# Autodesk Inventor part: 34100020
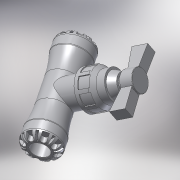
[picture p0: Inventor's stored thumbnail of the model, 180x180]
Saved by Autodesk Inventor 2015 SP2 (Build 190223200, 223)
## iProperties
Created: 2016-12
Part Number: 34100020
Material: PVC-Piping
Description: Plasson COMPRESSION STOPTAP 20 SERIES 1
Document SubType Name: Modeling
Designer: KIM
Mass: 61.7504 g
Surface Area: 140.097 cm^2
Volume: 44.1074 cm^3
Density: 1.4 g/cm^3
Appearance: Smooth - White
Author: KIM
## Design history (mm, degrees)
derived "03410.ipt"
feature "Solid1::03410.ipt" dims "ScaleForDerivedMember" = 10
feature "Solid2::03410.ipt" dims "ScaleForDerivedMember" = 10
tag "TaggingFeature1"
body "Solid1"
other parameters: "d1" = 18.9 [user parameter], "d3" = 25 [user parameter], "d4" = 41 [user parameter], "d6" = 45 [user parameter], "d8" = 34.85 [user parameter], "d13" = 6.4 [user parameter], "d14" = 6.4 [user parameter], "d15" = 0 [user parameter], "d17" = 360 deg [user parameter], "d19" = 8 deg [user parameter], "d20" = 0.4 [user parameter], "d21" = 0.4 [user parameter], "d22" = 8 deg [user parameter], "d24" = 0 [user parameter], "d26" = 360 deg [user parameter], "d33" = 4.1 [user parameter], "d35" = 2.5 [user parameter], "d65" = 0.41 [user parameter], "d69" = 123 [user parameter], "d72" = 41 [user parameter], "d73" = 25 [user parameter], "d74" = 18.9 [user parameter], "d75" = 61.5 [user parameter], "d76" = 2.5 [user parameter], "d77" = 45 [user parameter], "d80" = 6.4 [user parameter], "d82" = 6.4 [user parameter], "d83" = 0 [user parameter], "d85" = 360 deg [user parameter], "d92" = 0 [user parameter], "d94" = 360 deg [user parameter], "d96" = 89 [user parameter], "d97" = 41 [user parameter], "d98" = 32.8 [user parameter], "d99" = 32.8 [user parameter], "d100" = 135 deg [user parameter], "d101" = 16.4 [user parameter], "d102" = 70 deg [user parameter], "d103" = 48.95 [user parameter], "d104" = 71.2 [user parameter], "d105" = 62.3 [user parameter], "d107" = 75.65 [user parameter], "d108" = 73.8 [user parameter], "d110" = 12.015 [user parameter], "d111" = 4.005 [user parameter], "d112" = 12.3 [user parameter], "d113" = 0 [user parameter], "d114" = 43.05 [user parameter], "d115" = 4.1 [user parameter], "d116" = 0 [user parameter], "d117" = 4.1 [user parameter], "d119" = 0 [user parameter], "d121" = 360 deg [user parameter], "d126" = 0.4 [user parameter], "d127" = 0.4 [user parameter], "d128" = 8 deg [user parameter], "d129" = 8 deg [user parameter], "d130" = 0.41 [user parameter], "d132" = 0 [user parameter], "E_" = 41 [user parameter], "H_" = 123 [user parameter], "l_" = 45 [user parameter], "A_" = 89 [user parameter], "l_1" = 45 [user parameter], "E_1" = 41 [user parameter], "d9" = 8 [user parameter], "d11" = 41 [user parameter], "d12" = 25 [user parameter], "d78" = 41 [user parameter], "d79" = 25 [user parameter], "d81" = 8 [user parameter], "d109" = 13.35 [user parameter]
